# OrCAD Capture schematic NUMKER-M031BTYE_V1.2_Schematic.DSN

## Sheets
1 Nu-Link2-Me: size A3; title: Nu-Link2-Me; rev: 1.0; company: CMHuang; note: Nu-Link2-Me
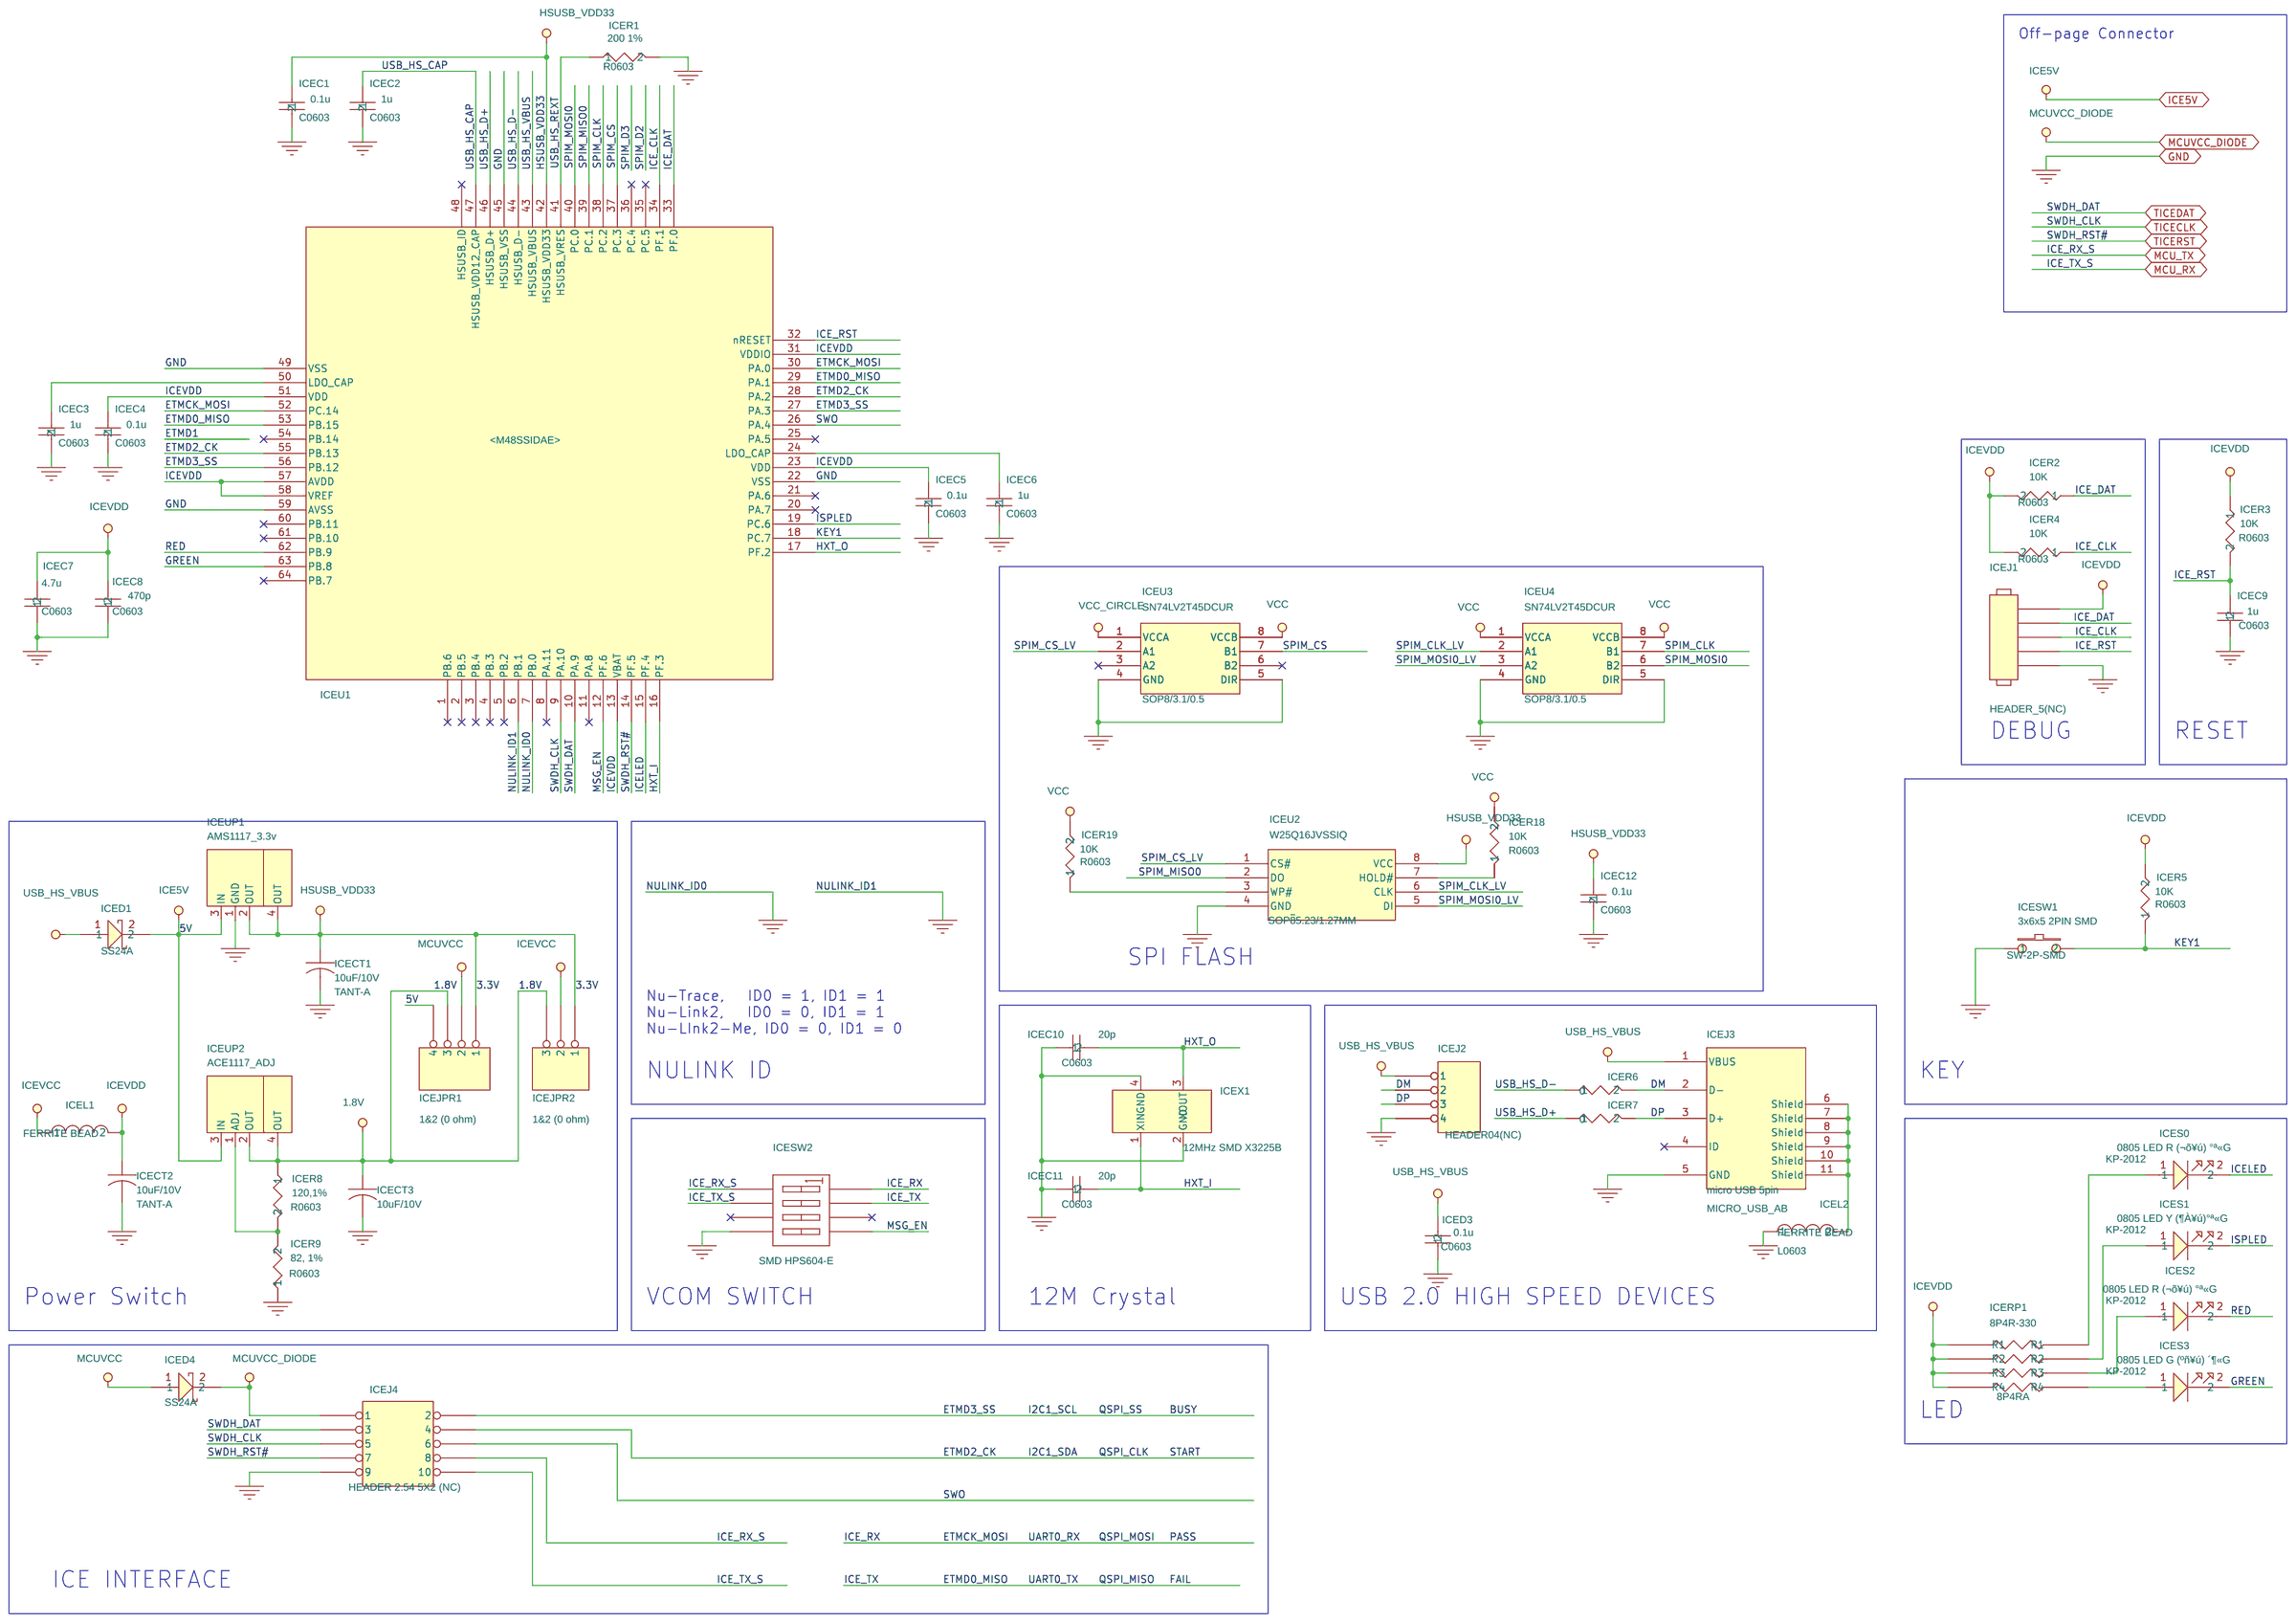
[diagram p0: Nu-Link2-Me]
2 M031BTYE3AN: size Custom; title: M031BTYE3AN; rev: v1.2; note: NuMaker-M031BTYE
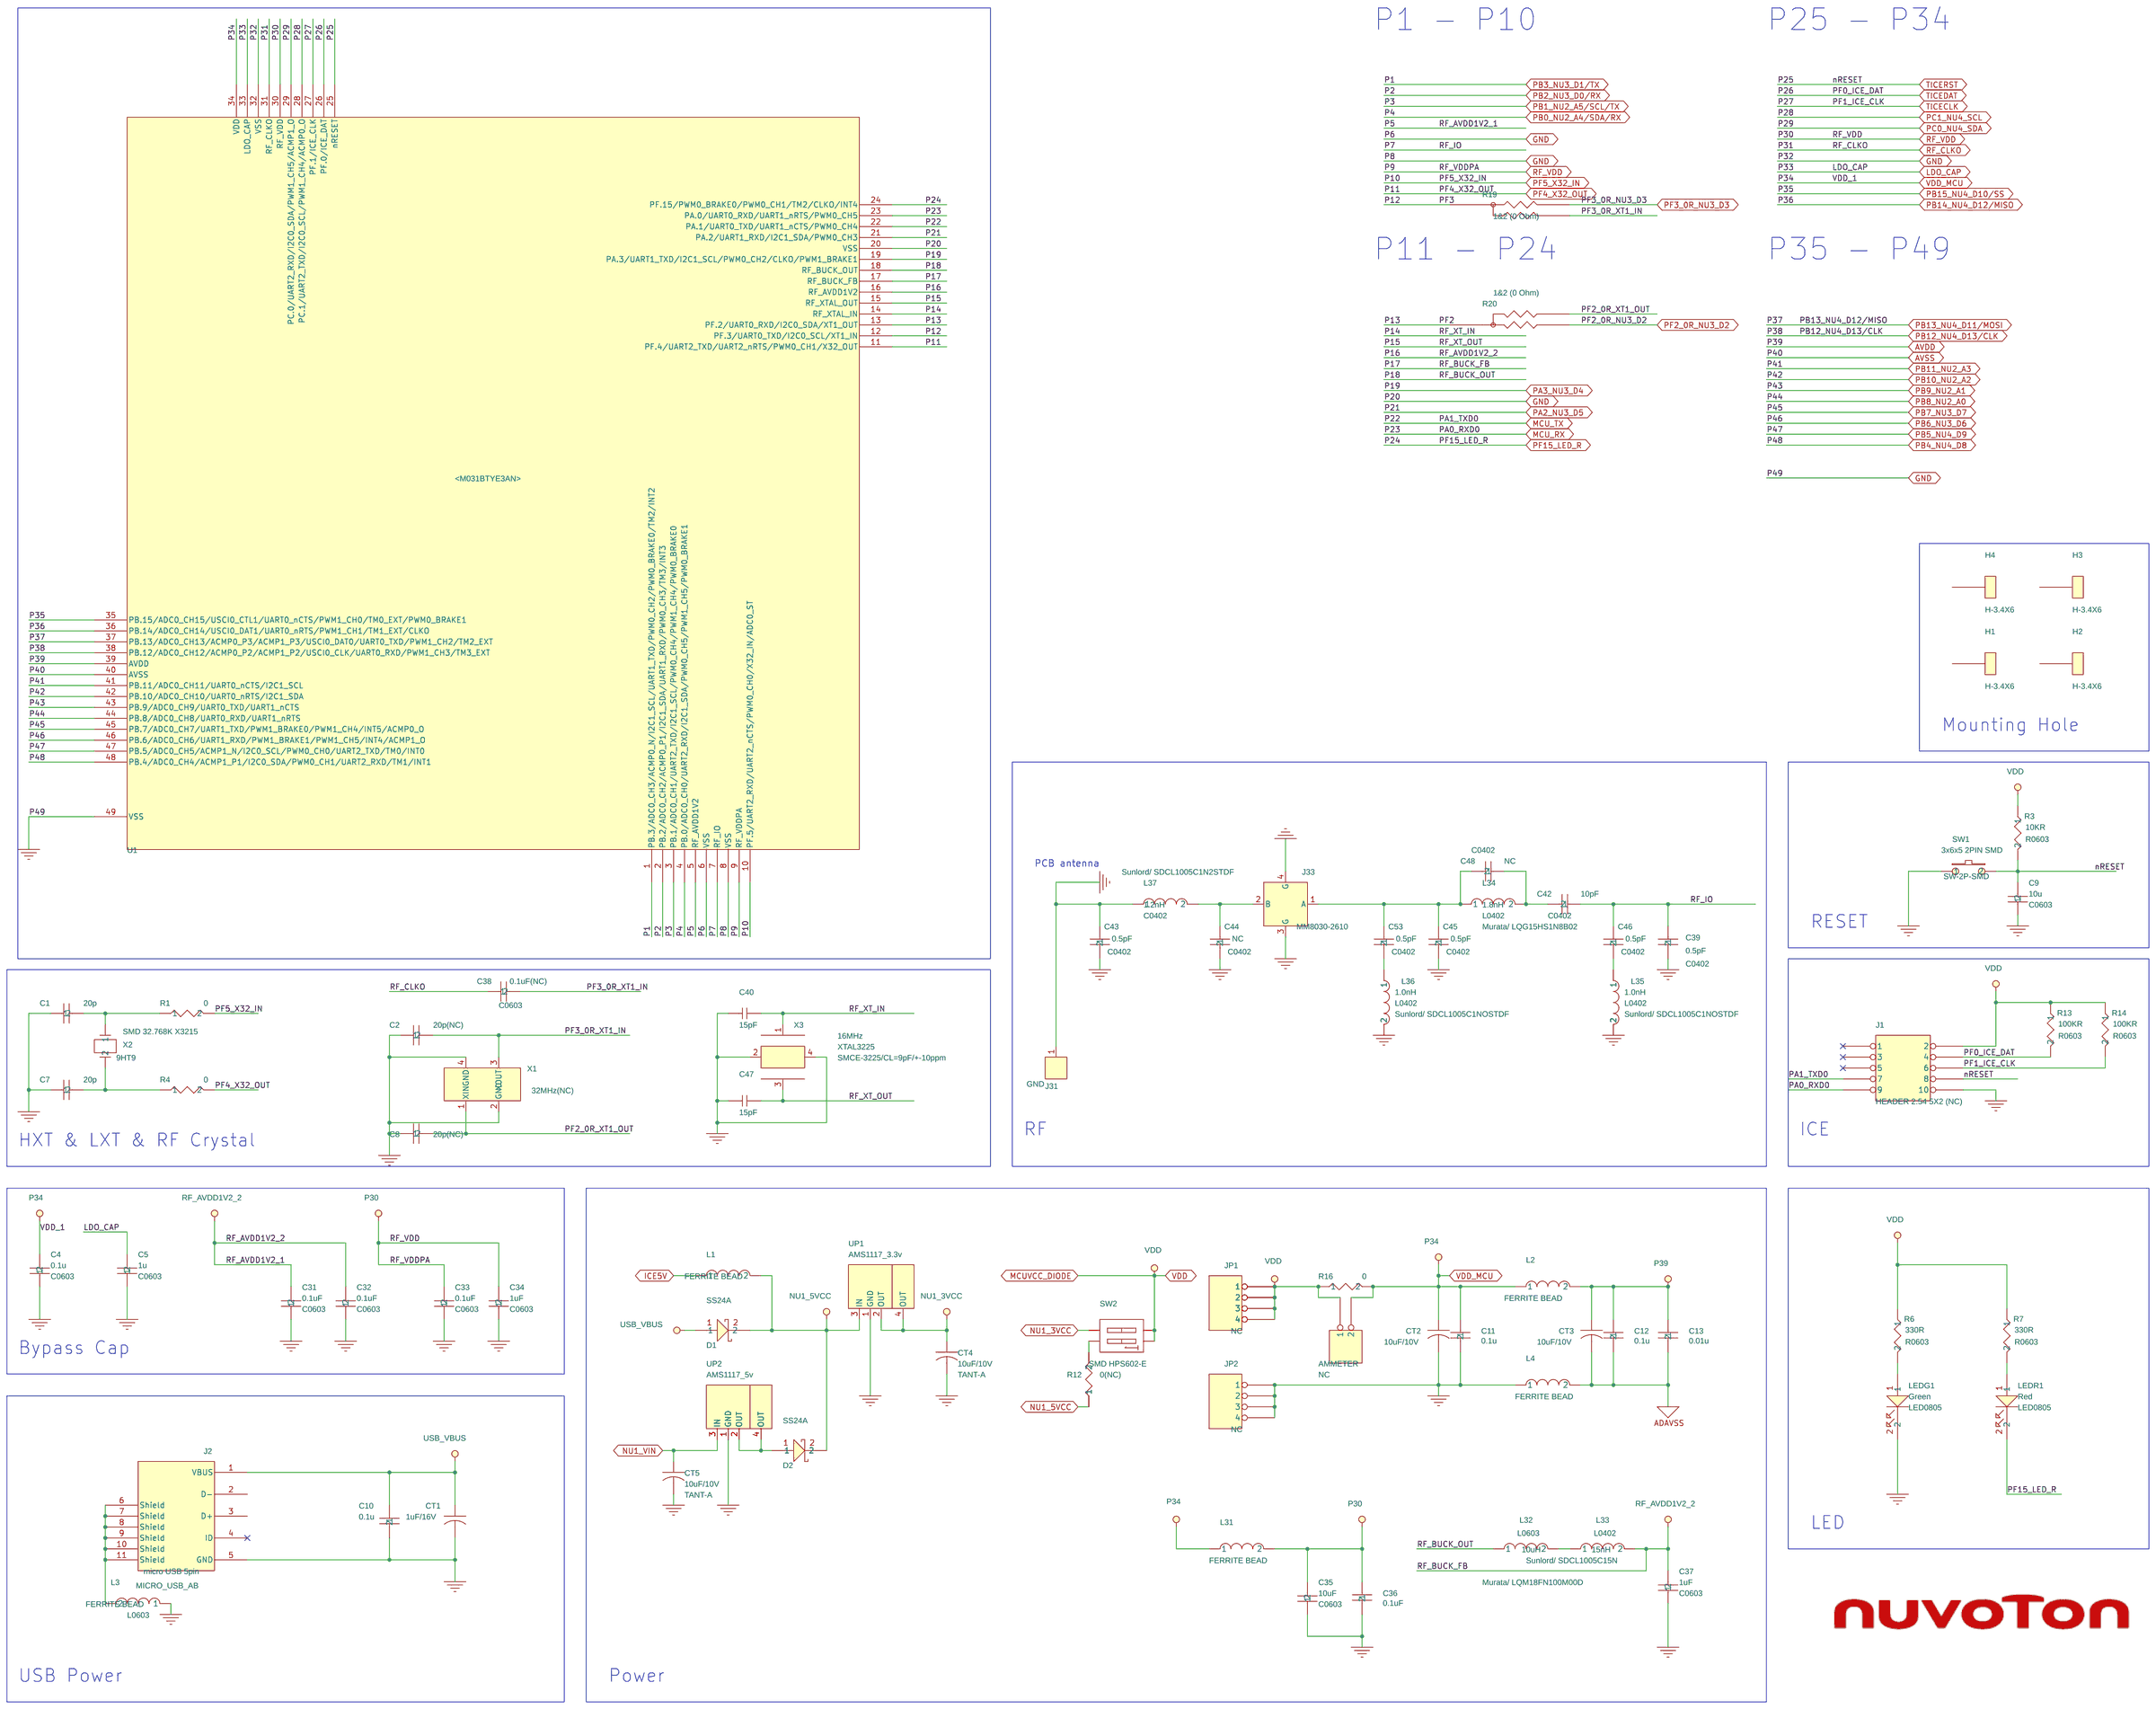
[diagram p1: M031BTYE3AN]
3 Ext. Connector: size Custom; title: Ext. Connector; rev: v1.2; note: NuMaker-M031BTYE
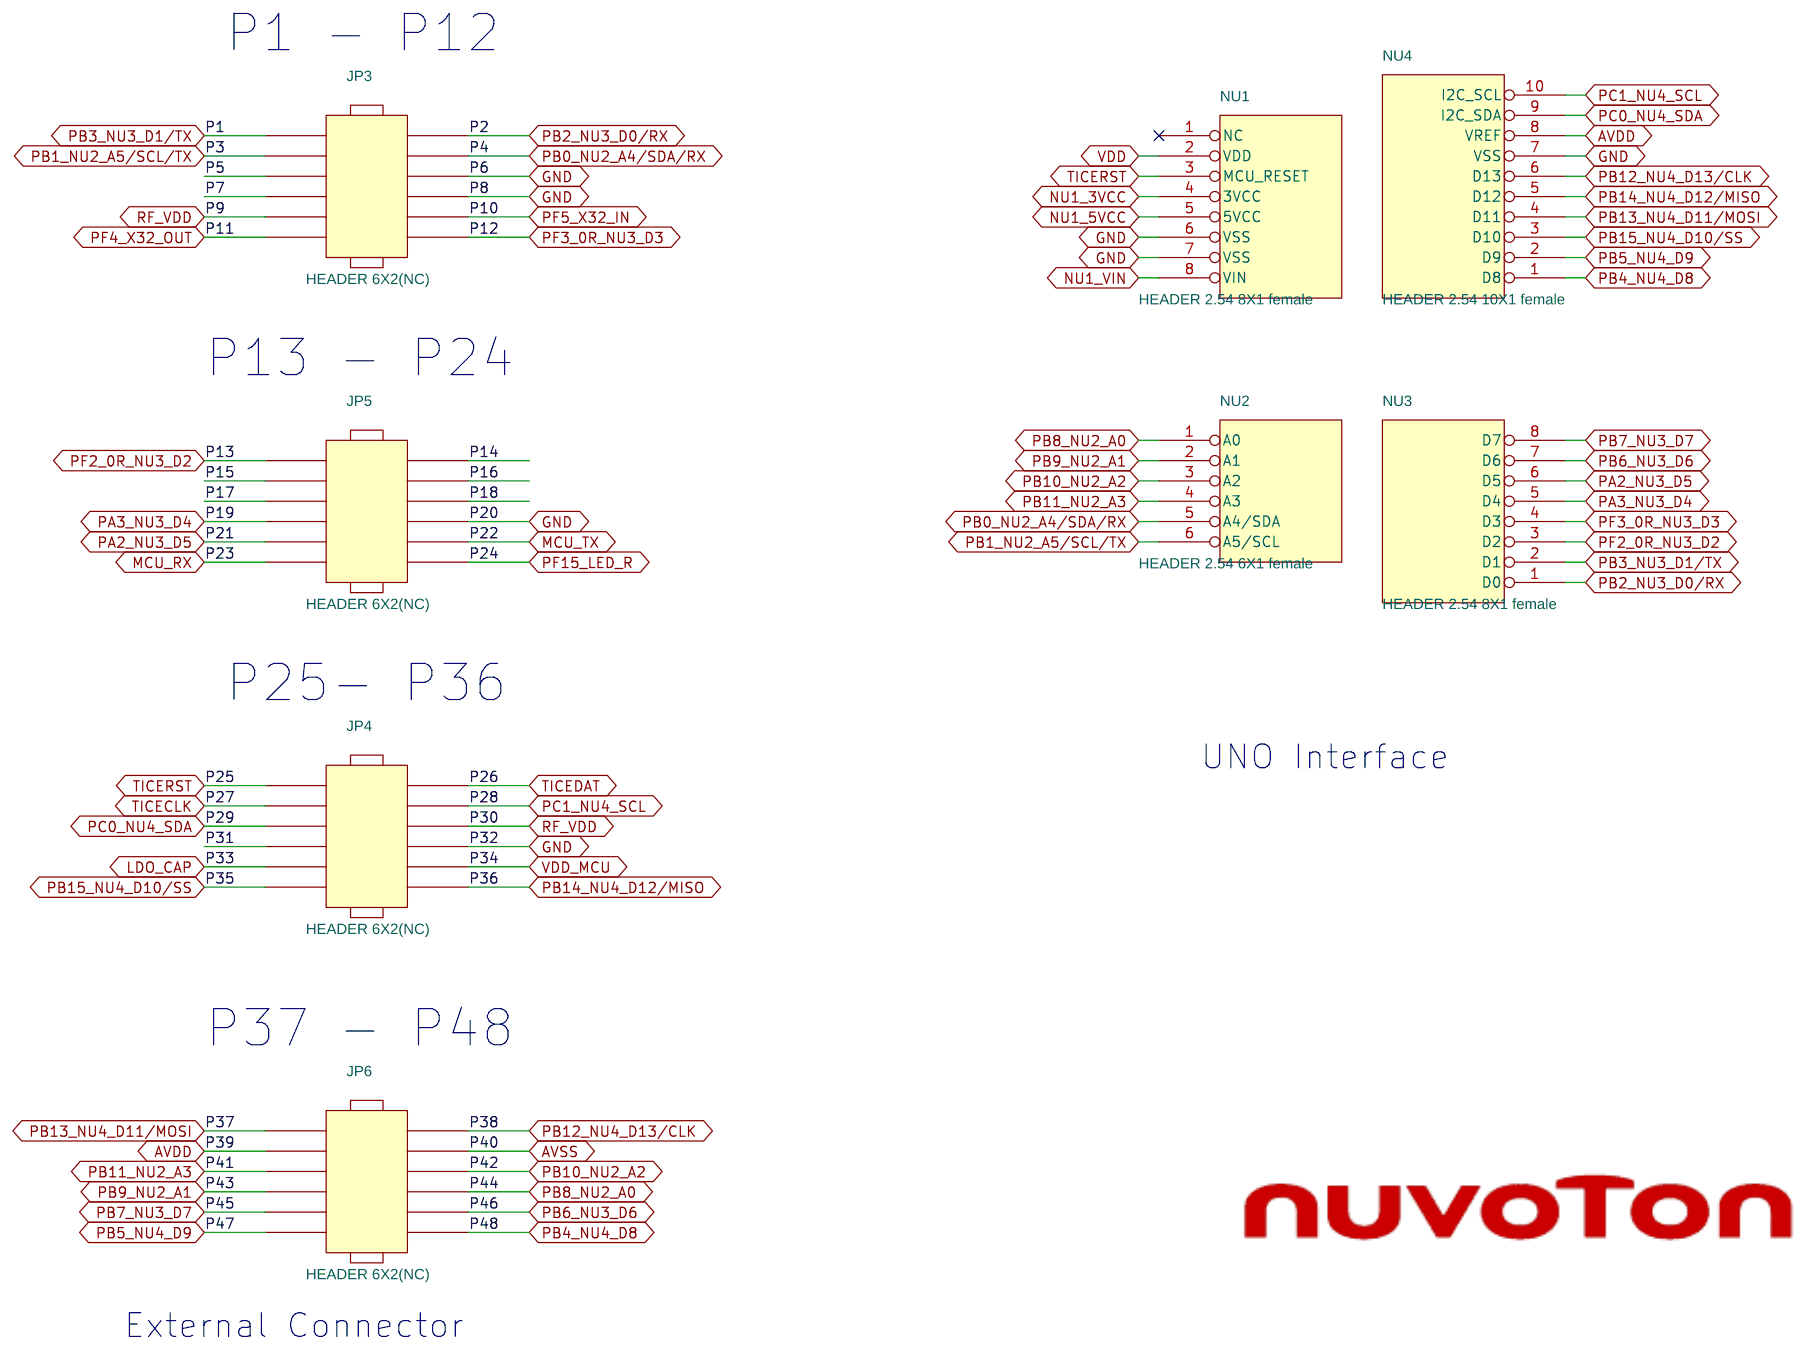
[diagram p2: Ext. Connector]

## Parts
sheet Ext. Connector
JP3  HEADER 6X2(NC)  [HEADER6X2]
JP4  HEADER 6X2(NC)  [HEADER6X2]
JP5  HEADER 6X2(NC)  [HEADER6X2]
JP6  HEADER 6X2(NC)  [HEADER6X2]
NU1  HEADER 2.54 8X1 female  [SIP-8P]
NU2  HEADER 2.54 6X1 female  [SIP-6P]
NU3  HEADER 2.54 8X1 female  [SIP-8P]
NU4  HEADER 2.54 10X1 female  [SIP-10P]
sheet M031BTYE3AN
AMMETER  NC
C1  20p  [C0603]
C2  20p(NC)  [C0603]
C4  0.1u  [C0603]
C5  1u  [C0603]
C7  20p  [C0603]
C8  20p(NC)  [C0603]
C9  10u  [C0603]
C10  0.1u  [C0603]
C11  0.1u  [C0603]
C12  0.1u  [C0603]
C13  0.01u  [C0603]
C31  0.1uF  [C0603]
C32  0.1uF  [C0603]
C33  0.1uF  [C0603]
C34  1uF  [C0603]
C35  10uF  [C0603]
C36  0.1uF  [C0603]
C37  1uF  [C0603]
C38  0.1uF(NC)  [C0603]
C39  0.5pF  [C0402]
C40  15pF  [C0402]
C42  10pF  [C0402]
C43  0.5pF  [C0402]
C44  NC  [C0402]
C45  0.5pF  [C0402]
C46  0.5pF  [C0402]
C47  15pF  [C0402]
C48  NC  [C0402]
C53  0.5pF  [C0402]
CT1  1uF/16V  [TANT-A]
CT2  10uF/10V  [TANT-A]
CT3  10uF/10V  [TANT-A]
CT4  10uF/10V  [TANT-A]
CT5  10uF/10V  [TANT-A]
D1  SS24A  [RB060L]
D2  SS24A  [RB060L]
H1  H-3.4X6  [H-3.4X6]
H2  H-3.4X6  [H-3.4X6]
H3  H-3.4X6  [H-3.4X6]
H4  H-3.4X6  [H-3.4X6]
J1  HEADER 2.54 5X2 (NC)  [HEADER5X2]
J2  micro USB 5pin  [MICRO_USB_AB]
J31  GND  [antenna_p]
J33  MM8030-2610  [MM8030-2610]
JP1  NC  [header1x4]
JP2  NC  [header1x4]
L1  FERRITE BEAD  [L0603]
L2  FERRITE BEAD  [L0603]
L3  FERRITE BEAD  [L0603]
L4  FERRITE BEAD  [L0603]
L31  FERRITE BEAD  [L0603]
L32  10uH  [L0603]
L33  15nH  [L0402]
L34  1.8nH  [L0402]
L35  1.0nH  [L0402]
L36  1.0nH  [L0402]
L37  1.2nH  [C0402]
LEDG1  Green  [LED0805]
LEDR1  Red  [LED0805]
R1  0  [R0603]
R3  10KR  [R0603]
R4  0  [R0603]
R6  330R  [R0603]
R7  330R  [R0603]
R12  0(NC)  [R0603]
R13  100KR  [R0603]
R14  100KR  [R0603]
R16  0  [R0603]
R19  1&2 (0 Ohm)  [R0603X2]
R20  1&2 (0 Ohm)  [R0603X2]
SW1  3x6x5 2PIN SMD  [SW-2P-SMD]
SW2  SMD HPS602-E  [SW1X2]
U1  M031BTYE3AN  [MCU_QFN48_5X5mm]
UP1  AMS1117_3.3v  [SOT-223-1]
UP2  AMS1117_5v  [SOT-223-1]
X1  32MHz(NC)  [XTAL3225]
X2  SMD 32.768K X3215  [9HT9]
X3  16MHz  [XTAL3225]
sheet Nu-Link2-Me
ICEC1  0.1u  [C0603]
ICEC2  1u  [C0603]
ICEC3  1u  [C0603]
ICEC4  0.1u  [C0603]
ICEC5  0.1u  [C0603]
ICEC6  1u  [C0603]
ICEC7  4.7u  [C0603]
ICEC8  470p  [C0603]
ICEC9  1u  [C0603]
ICEC10  20p  [C0603]
ICEC11  20p  [C0603]
ICEC12  0.1u  [C0603]
ICECT1  10uF/10V  [TANT-A]
ICECT2  10uF/10V  [TANT-A]
ICECT3  10uF/10V  [TANT-A]
ICED1  SS24A  [RB060L]
ICED3  0.1u  [C0603]
ICED4  SS24A  [RB060L]
ICEJ1  HEADER_5(NC)  [HEADER5X1]
ICEJ2  HEADER04(NC)  [HEADER04]
ICEJ3  micro USB 5pin  [MICRO_USB_AB]
ICEJ4  HEADER 2.54 5X2 (NC)  [HEADER5X2]
ICEJPR1  1&2 (0 ohm)  [R0603X3]
ICEJPR2  1&2 (0 ohm)  [R0603X2]
ICEL1  FERRITE BEAD  [L0603]
ICEL2  FERRITE BEAD  [L0603]
ICER1  200 1%  [R0603]
ICER2  10K  [R0603]
ICER3  10K  [R0603]
ICER4  10K  [R0603]
ICER5  10K  [R0603]
ICER6  0  [R0603]
ICER7  0  [R0603]
ICER8  120,1%  [R0603]
ICER9  82, 1%  [R0603]
ICER18  10K  [R0603]
ICER19  10K  [R0603]
ICERP1  8P4R-330  [8P4RA]
ICES0  0805 LED R (¬õ¥ú) °ª«G  [KP-2012]
ICES1  0805 LED Y (¶À¥ú)°ª«G  [KP-2012]
ICES2  0805 LED R (¬õ¥ú) °ª«G  [KP-2012]
ICES3  0805 LED G (ºñ¥ú) ´¶«G  [KP-2012]
ICESW1  3x6x5 2PIN SMD  [SW-2P-SMD]
ICESW2  SMD HPS604-E  [SW1X4]
ICEU1  M48SSIDAE  [LQFP64_7x7_M48SSIDAE]
ICEU2  W25Q16JVSSIQ  [SOP8\5.23/1.27MM]
ICEU3  SN74LV2T45DCUR  [SOP8/3.1/0.5]
ICEU4  SN74LV2T45DCUR  [SOP8/3.1/0.5]
ICEUP1  AMS1117_3.3v  [SOT-223-1]
ICEUP2  ACE1117_ADJ  [SOT-223-1]
ICEX1  12MHz SMD X3225B  [CRYSTAL_SMD]

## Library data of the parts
JP3-JP6 = HEADER_6X2
NU1 = POWER_CONNECT_0
NU2 = ADC_CONNECT_0
NU3 = PWM0_CONNECT_0
NU4 = PWM1_CONNECT_1
AMMETER = HEADER_2
C1 = C_20p_2
C2 = C_20p_3
C4 = CAP-C_8: Package: 0603; element_no: C0004
C5 = CAP-C_9: Package: 0603; element_no: C0006
C7 = C_20p_4
C8 = C_20p_1
C9 = CAP-C_2: Package: 0603; element_no: C0006
C10 = C_0.1u: element_no: C0004
C11 = C_0.1u_3: element_no: C0004
C12 = C_0.1u_2: element_no: C0004
C13 = C_0.1u_1: element_no: C0003
C31 ICED3 = CAP-C: Package: 0603; element_no: C0004
C32 ICEC5 = CAP-C_12: Package: 0603; element_no: C0004
C33 = CAP-C_14: Package: 0603; element_no: C0004
C34 = CAP-C_7: Package: 0603; element_no: C0004
C35 ICEC3 = CAP-C_10: Package: 0603; element_no: C0006
C36 = C_0.1u_4: element_no: C0004
C37 = CAP-C_16: Package: 0603; element_no: C0006
C38 = C_20p
C39 = CAP-C_13: Package: 0603
C40 C47 = CAPACITOR
C42 ICEC8 = CAP-C_1: Package: 0603
C43 = CAP-C_3: Package: 0603
C44 = CAP-C_4: Package: 0603
C45 = CAP-C_11: Package: 0603
C46 = CAP-C_5: Package: 0603
C48 = CAP-C_6: Package: 0603
C53 = CAP-C_15: Package: 0603
CT1 = C_1uF_16V
CT2-CT5 ICECT1-ICECT3 = C_10uF_10V
D1 ICED4 = D_SS24A_1
D2 ICED1 = D_SS24A
H1-H4 = TEST_POINT
ICEJ4 J1 = HEADER_5X2
ICEJ3 J2 = micro_USB_5pin_0
J31 = JUMPER3X1_0
J33 = JUMPER3X1_4
ICEJ2 JP1 = HEADER_4
JP2 = HEADER_4_1
ICEL2 L1 = FERRITE_BEAD_1
L2 = FERRITE_BEAD_3
L3 = FERRITE_BEAD_4
ICEL1 L4 = FERRITE_BEAD
L31 = FERRITE_BEAD_2
L32 = INDUCTOR_1: Part Number: Murata/ LQM18FN100M00D
L33 = INDUCTOR: Package: L0603; Part Number: Sunlord/ SDCL1005C15N
L34 = INDUCTOR_3: Package: L0603; Part Number: Murata/ LQG15HS1N8B02
L35 = INDUCTOR_2: Package: L0603; Part Number: Sunlord/ SDCL1005C1NOSTDF
L36 = INDUCTOR_5: Package: L0603; Part Number: Sunlord/ SDCL1005C1NOSTDF
L37 = INDUCTOR_4: Package: L0603; Part Number: Sunlord/ SDCL1005C1N2STDF
LEDG1 = LED_0_1: Package: KP-2012; Vendor: Kingbright
LEDR1 = LED_0: Package: KP-2012; Vendor: Kingbright
R1 = R_0_7
ICER9 R3 = R_0: Package: 0603
R4 = R_0_4
ICER1 R6 = R_0_6: Package: 0603
ICER5 R7 = R_0_2: Package: 0603
R12 = R_0_1
ICER8 R13 = R_0_3: Package: 0603
ICER2 R14 = R_0_5: Package: 0603
R16 = R_0_8
R19 R20 = RESISTOR_SIP_3_0
ICESW1 SW1 = SW_PUSHBUTTON_0
SW2 = SW_DIP-4_2
U1 = M031BTYE3AN_4: M031LE3AE: <M031BTYE3AN>
ICEUP1 UP1 UP2 = TO-247_Regulator_10
X1 = Crystal_SMD_3
X2 = Xtal_32.768K
X3 = X_0: Part Number: SMCE-3225/CL=9pF/+-10ppm
ICEC1 = CAP-C_4: Package: 0603; element_no: C0004
ICEC2 = CAP-C_6: Package: 0603; element_no: C0006
ICEC4 = CAP-C_11: Package: 0603; element_no: C0004
ICEC6 = CAP-C_5: Package: 0603; element_no: C0006
ICEC7 = CAP-C_9: Package: 0603
ICEC9 = CAP-C_8: Package: 0603; element_no: C0006
ICEC10 = CAP-C_7: Package: 0603
ICEC11 = CAP-C_2: Package: 0603
ICEC12 = CAP-C_3: Package: 0603; element_no: C0004
ICEJ1 = HEADER_5
ICEJPR1 = HEADER_3_0
ICEJPR2 = HEADER_3
ICER3 = R_0_7: Package: 0603
ICER4 = R_0_8: Package: 0603
ICER6 = R_33
ICER7 = R_33_1
ICER18 = R_0_4: Package: 0603
ICER19 = R_0_1: Package: 0603
ICERP1 = R-PACK8_0
ICES0 = LED_0_1: Vendor: Kingbright
ICES1 = LED_0: Vendor: Kingbright
ICES2 = LED_0_2: Vendor: Kingbright
ICES3 = LED_0_3: Vendor: Kingbright
ICESW2 = SW_DIP-4_SM
ICEU1 = M487SIDAE_0: M487SIDAE: <M48SSIDAE>
ICEU2 = W25P10_20_40_SOIC_0: Package: SOP8; Vendor: WINBOND
ICEU3 ICEU4 = SN74LV2T45
ICEUP2 = TO-247_Regulator_0
ICEX1 = Crystal_SMD_4

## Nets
1.8V: ICECT3.1 ICEJPR1.3 ICEJPR2.3 ICER8.1 ICEUP2.2(OUT) ICEUP2.4(OUT)
3.3V: ICEC1.1 ICEC12.1 ICECT1.1 ICEJPR1.1 ICEJPR2.1 ICER18.2 ICER19.2 ICEU1.42(HSUSB_VDD33) ICEU2.8(VCC) ICEU3.1(VCCA) ICEU4.1(VCCA) ICEUP1.2(OUT) ICEUP1.4(OUT)
AVDD: C12.1 C13.1 CT3.1 JP6.3 L2.2 NU4.8(VREF) U1.39(AVDD)
AVSS: C12.2 C13.2 CT3.2 JP6.4 L4.2 U1.40(AVSS)
GND: C1.1 C2.1 C4.1 C5.1 C7.1 C8.1 C9.1 C10.2 C11.2 C31.1 C32.1 C33.1 C34.1 C35.1 C36.2 C37.1 C39.2 C40.1 C43.1 C43.2 C44.2 C45.2 C47.1 CT1.2 CT2.2 CT4.2 CT5.2 ICEC1.2 ICEC2.2 ICEC3.2 ICEC4.2 ICEC5.2 ICEC6.2 ICEC7.1 ICEC8.1 ICEC9.1 ICEC10.1 ICEC11.1 ICEC12.2 ICECT1.2 ICECT2.2 ICECT3.2 ICED3.1 ICEJ1.5 ICEJ2.4 ICEJ3.5(GND) ICEJ4.9 ICEL2.1 ICER1.2 ICER9.1 ICESW1.1 ICESW2.4(A4) ICEU1.6(PB.1) ICEU1.7(PB.0) ICEU1.22(VSS) ICEU1.45(HSUSB_VSS) ICEU1.49(VSS) ICEU1.59(AVSS) ICEU2.4(GND) ICEU3.4(GND) ICEU3.5(DIR) ICEU4.4(GND) ICEU4.5(DIR) ICEUP1.1(GND) ICEX1.2(GND) ICEX1.4(GND) J1.10 J2.5(GND) J31.1 J33.3(G) J33.4(G) JP2.1 JP2.2 JP2.3 JP2.4 JP3.6 JP3.8 JP4.8 JP5.8 L3.1 L4.1 L35.2 L36.2 L37.1 LEDG1.2 NU1.6(VSS) NU1.7(VSS) NU4.7(VSS) SW1.1 U1.6(VSS) U1.8(VSS) U1.20(VSS) U1.32(VSS) U1.49(VSS) UP1.1(GND) UP2.1(GND) X1.2(GND) X1.4(GND) X3.2 X3.4
VDD: AMMETER.1 ICED4.2 ICEJ4.1 J1.2 JP1.1 JP1.2 JP1.3 JP1.4 NU1.2(VDD) R3.1 R6.1 R7.1 R13.1 R14.1 R16.1 SW2.3(B1) SW2.4(B2)
VDD_MCU: AMMETER.2 C4.2 C11.1 CT2.1 JP4.10 L2.1 L31.1 R16.2 U1.34(VDD)
BUSY: ICEJ4.2 ICEU1.27(PA.3) ICEU1.56(PB.12)
DM: ICEJ2.2 ICEJ3.2(D-) ICER6.2
DP: ICEJ2.3 ICEJ3.3(D+) ICER7.2
ETMD2_CK: ICEJ4.4 ICEU1.28(PA.2) ICEU1.55(PB.13)
GREEN: ICES3.2 ICEU1.63(PB.8)
HXT_I: ICEC11.2 ICEU1.16(PF.3) ICEX1.1(XIN)
HXT_O: ICEC10.2 ICEU1.17(PF.2) ICEX1.3(XOUT)
ICE5V: ICED1.2 ICEJPR1.4 ICEUP1.3(IN) ICEUP2.3(IN) L1.1
ICE_CLK: ICEJ1.3 ICER4.1 ICEU1.34(PF.1)
ICE_DAT: ICEJ1.2 ICER2.1 ICEU1.33(PF.0)
ICE_RST: ICEC9.2 ICEJ1.4 ICER3.2 ICEU1.32(nRESET)
ICE_RX: ICESW2.8(B1) ICEU1.30(PA.0) ICEU1.52(PC.14)
ICE_TX: ICESW2.7(B2) ICEU1.29(PA.1) ICEU1.53(PB.15)
ICELED: ICES0.2 ICEU1.15(PF.4)
ICEVCC: ICEJPR2.2 ICEL1.1
ICEVDD: ICEC4.1 ICEC5.1 ICEC7.2 ICEC8.2 ICECT2.1 ICEJ1.1 ICEL1.2 ICER2.2 ICER3.1 ICER4.2 ICER5.2 ICERP1.1(R1) ICERP1.3(R2) ICERP1.5(R3) ICERP1.7(R4) ICEU1.13(VBAT) ICEU1.23(VDD) ICEU1.31(VDDIO) ICEU1.51(VDD) ICEU1.57(AVDD) ICEU1.58(VREF) ICEU3.8(VCCB) ICEU4.8(VCCB)
ISPLED: ICES1.2 ICEU1.19(PC.6)
KEY1: ICER5.1 ICESW1.2 ICEU1.18(PC.7)
LDO_CAP: C5.2 JP4.9 U1.33(LDO_CAP)
MCU_RX: ICEJ4.10 ICESW2.2(A2) J1.9 JP5.11 U1.23(PA.0/UART0_RXD/UART1_nRTS/PWM0_CH5)
MCU_TX: ICEJ4.8 ICESW2.1(A1) J1.7 JP5.10 U1.22(PA.1/UART0_TXD/UART1_nCTS/PWM0_CH4)
MCUVCC: ICED4.1 ICEJPR1.2
MSG_EN: ICESW2.5(B4) ICEU1.12(PF.6)
NU1_3VCC: CT4.1 NU1.4(3VCC) SW2.2(A2) UP1.2(OUT) UP1.4(OUT)
NU1_5VCC: D1.2 D2.2 L1.2 NU1.5(5VCC) R12.1 UP1.3(IN)
NU1_VIN: CT5.1 NU1.8(VIN) UP2.3(IN)
P5: JP3.5
P7: C39.1 C42.1 C46.1 U1.7(RF_IO)
P7 (page 03-Ext. Connector): JP3.7
P14: C40.2 U1.14(RF_XTAL_IN) X3.1
P14 (page 03-Ext. Connector): JP5.2
P15: C47.2 U1.15(RF_XTAL_OUT) X3.3
P15 (page 03-Ext. Connector): JP5.3
P16: JP5.4
P17: JP5.5
P18: L32.1 U1.18(RF_BUCK_OUT)
P18 (page 03-Ext. Connector): JP5.6
P31: JP4.7
PA2_NU3_D5: JP5.9 NU3.6(D5) U1.21(PA.2/UART1_RXD/I2C1_SDA/PWM0_CH3)
PA3_NU3_D4: JP5.7 NU3.5(D4) U1.19(PA.3/UART1_TXD/I2C1_SCL/PWM0_CH2/CLKO/PWM1_BRAKE1)
PB0_NU2_A4/SDA/RX: JP3.4 NU2.5(A4/SDA) U1.4(PB.0/ADC0_CH0/UART2_RXD/I2C1_SDA/PWM0_CH5/PWM1_CH5/PWM0_BRAKE1)
PB1_NU2_A5/SCL/TX: JP3.3 NU2.6(A5/SCL) U1.3(PB.1/ADC0_CH1/UART2_TXD/I2C1_SCL/PWM0_CH4/PWM1_CH4/PWM0_BRAKE0)
PB2_NU3_D0/RX: JP3.2 NU3.1(D0) U1.2(PB.2/ADC0_CH2/ACMP0_P1/I2C1_SDA/UART1_RXD/PWM0_CH3/TM3/INT3)
PB3_NU3_D1/TX: JP3.1 NU3.2(D1) U1.1(PB.3/ADC0_CH3/ACMP0_N/I2C1_SCL/UART1_TXD/PWM0_CH2/PWM0_BRAKE0/TM2/INT2)
PB4_NU4_D8: JP6.12 NU4.1(D8) U1.48(PB.4/ADC0_CH4/ACMP1_P1/I2C0_SDA/PWM0_CH1/UART2_RXD/TM1/INT1)
PB5_NU4_D9: JP6.11 NU4.2(D9) U1.47(PB.5/ADC0_CH5/ACMP1_N/I2C0_SCL/PWM0_CH0/UART2_TXD/TM0/INT0)
PB6_NU3_D6: JP6.10 NU3.7(D6) U1.46(PB.6/ADC0_CH6/UART1_RXD/PWM1_BRAKE1/PWM1_CH5/INT4/ACMP1_O)
PB7_NU3_D7: JP6.9 NU3.8(D7) U1.45(PB.7/ADC0_CH7/UART1_TXD/PWM1_BRAKE0/PWM1_CH4/INT5/ACMP0_O)
PB8_NU2_A0: JP6.8 NU2.1(A0) U1.44(PB.8/ADC0_CH8/UART0_RXD/UART1_nRTS)
PB9_NU2_A1: JP6.7 NU2.2(A1) U1.43(PB.9/ADC0_CH9/UART0_TXD/UART1_nCTS)
PB10_NU2_A2: JP6.6 NU2.3(A2) U1.42(PB.10/ADC0_CH10/UART0_nRTS/I2C1_SDA)
PB11_NU2_A3: JP6.5 NU2.4(A3) U1.41(PB.11/ADC0_CH11/UART0_nCTS/I2C1_SCL)
PB12_NU4_D13/CLK: JP6.2 NU4.6(D13) U1.38(PB.12/ADC0_CH12/ACMP0_P2/ACMP1_P2/USCI0_CLK/UART0_RXD/PWM1_CH3/TM3_EXT)
PB13_NU4_D11/MOSI: JP6.1 NU4.4(D11) U1.37(PB.13/ADC0_CH13/ACMP0_P3/ACMP1_P3/USCI0_DAT0/UART0_TXD/PWM1_CH2/TM2_EXT)
PB14_NU4_D12/MISO: JP4.12 NU4.5(D12) U1.36(PB.14/ADC0_CH14/USCI0_DAT1/UART0_nRTS/PWM1_CH1/TM1_EXT/CLKO)
PB15_NU4_D10/SS: JP4.11 NU4.3(D10) U1.35(PB.15/ADC0_CH15/USCI0_CTL1/UART0_nCTS/PWM1_CH0/TM0_EXT/PWM0_BRAKE1)
PC0_NU4_SDA: JP4.5 NU4.9(I2C_SDA) U1.29(PC.0/UART2_RXD/I2C0_SDA/PWM1_CH5/ACMP1_O)
PC1_NU4_SCL: JP4.4 NU4.10(I2C_SCL) U1.28(PC.1/UART2_TXD/I2C0_SCL/PWM1_CH4/ACMP0_O)
PF2: R20.2 U1.13(PF.2/UART0_RXD/I2C0_SDA/XT1_OUT)
PF2_0R_NU3_D2: JP5.1 NU3.3(D2) R20.1
PF2_0R_XT1_OUT: C8.2 R20.3 X1.1(XIN)
PF3: R19.2 U1.12(PF.3/UART0_TXD/I2C0_SCL/XT1_IN)
PF3_0R_NU3_D3: JP3.12 NU3.4(D3) R19.1
PF3_0R_XT1_IN: C2.2 C38.2 R19.3 X1.3(XOUT)
PF4_X32_OUT: JP3.11 R4.2 U1.11(PF.4/UART2_TXD/UART2_nRTS/PWM0_CH1/X32_OUT)
PF5_X32_IN: JP3.10 R1.2 U1.10(PF.5/UART2_RXD/UART2_nCTS/PWM0_CH0/X32_IN/ADC0_ST)
PF15_LED_R: JP5.12 LEDR1.2 U1.24(PF.15/PWM0_BRAKE0/PWM0_CH1/TM2/CLKO/INT4)
RED: ICES2.2 ICEU1.62(PB.9)
RF_AVDD1V2: C31.2 C32.2 C37.2 L33.2 U1.5(RF_AVDD1V2) U1.16(RF_AVDD1V2) U1.17(RF_BUCK_FB)
RF_CLKO: C38.1 U1.31(RF_CLKO)
RF_VDD: C33.2 C34.2 C35.2 C36.1 JP3.9 JP4.6 L31.2 U1.9(RF_VDDPA) U1.30(RF_VDD)
SPIM_CLK: ICEU1.38(PC.2) ICEU4.7(B1)
SPIM_CLK_LV: ICEU2.6(CLK) ICEU4.2(A1)
SPIM_CS: ICEU1.37(PC.3) ICEU3.7(B1)
SPIM_CS_LV: ICEU2.1(CS#) ICEU3.2(A1)
SPIM_MISO0: ICEU1.39(PC.1) ICEU2.2(DO)
SPIM_MOSI0: ICEU1.40(PC.0) ICEU4.6(B2)
SPIM_MOSI0_LV: ICEU2.5(DI) ICEU4.3(A2)
SWO: ICEJ4.6 ICEU1.26(PA.4)
TICECLK: ICEJ4.5 ICEU1.9(PA.10) J1.6 JP4.3 R14.2 U1.27(PF.1/ICE_CLK)
TICEDAT: ICEJ4.3 ICEU1.10(PA.9) J1.4 JP4.2 R13.2 U1.26(PF.0/ICE_DAT)
TICERST: C9.2 ICEJ4.7 ICEU1.14(PF.5) J1.8 JP4.1 NU1.3(MCU_RESET) R3.2 SW1.2 U1.25(nRESET)
USB_HS_CAP: ICEC2.1 ICEU1.47(HSUSB_VDD12_CAP)
USB_HS_D+: ICER7.1 ICEU1.46(HSUSB_D+)
USB_HS_D-: ICER6.1 ICEU1.44(HSUSB_D-)
USB_HS_REXT: ICER1.1 ICEU1.41(HSUSB_VRES)
USB_HS_VBUS: ICED1.1 ICED3.2 ICEJ2.1 ICEJ3.1(VBUS) ICEU1.43(HSUSB_VBUS)
USB_VBUS: C10.1 CT1.1 D1.1 J2.1(VBUS)
N17408794: ICEC6.1 ICEU1.24(LDO_CAP)
N17408892: ICEC3.1 ICEU1.50(LDO_CAP)
N17409469: ICER18.1 ICEU2.7(HOLD#)
N17409471: ICER19.1 ICEU2.3(WP#)
N17409655: ICEJ3.6(Shield) ICEJ3.7(Shield) ICEJ3.8(Shield) ICEJ3.9(Shield) ICEJ3.10(Shield) ICEJ3.11(Shield) ICEL2.2
N17409830: ICERP1.8(R4) ICES3.1
N17409832: ICERP1.6(R3) ICES2.1
N17409866: ICERP1.4(R2) ICES1.1
N17409872: ICERP1.2(R1) ICES0.1
N17410019: ICER8.2 ICER9.2 ICEUP2.1(ADJ)
N17412799: C53.2 L36.1
N17412801: C45.1 C48.2 C53.1 J33.1(A) L34.1
N17412817: C46.2 L35.1
N17412836: C42.2 C48.1 L34.2
N17413278: C1.2 R1.1 X2.1
N17413280: C7.2 R4.1 X2.2
N17413523: C44.1 J33.2(B) L37.2
N17413703: J2.6(Shield) J2.7(Shield) J2.8(Shield) J2.9(Shield) J2.10(Shield) J2.11(Shield) L3.2
N17414005: LEDG1.1 R6.2
N17414007: LEDR1.1 R7.2
N17414019: R12.2 SW2.1(A1)
N17414057: D2.1 UP2.2(OUT) UP2.4(OUT)
N17414383: L32.2 L33.1

Not connected (* = marked no-connect by the designer): H1 1; H2 1; H3 1; H4 1; ICEJ3 4(ID)*; ICESW2 3(A3)* 6(B3)*; ICEU1 1(PB.6)* 2(PB.5)* 3(PB.4)* 4(PB.3)* 5(PB.2)* 8(PA.11)* 11(PA.8)* 20(PA.7)* 21(PA.6)* 25(PA.5)* 35(PC.5)* 36(PC.4)* 48(HSUSB_ID)* 54(PB.14)* 60(PB.11)* 61(PB.10)* 64(PB.7)*; ICEU3 3(A2)* 6(B2)*; J1 1* 3* 5*; J2 2(D-) 3(D+) 4(ID)*; NU1 1(NC)*

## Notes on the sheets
sheet 1
- Off-page Connector
- DEBUG
- RESET
- SPI FLASH
- Nu-Trace,   ID0 = 1, ID1 = 1
  Nu-Link2,   ID0 = 0, ID1 = 1
  Nu-LInk2-Me, ID0 = 0, ID1 = 0
- NULINK ID
- KEY
- Power Switch
- VCOM SWITCH
- 12M Crystal
- USB 2.0 HIGH SPEED DEVICES
- LED
- ICE INTERFACE
sheet 2
- P1 - P10
- P25 - P34
- P11 - P24
- P35 - P49
- Mounting Hole
- PCB antenna
- RESET
- RF
- ICE
- HXT & LXT & RF Crystal
- Bypass Cap
- LED
- USB Power
- Power
sheet 3
- P1 - P12
- P13 - P24
- P25- P36
- UNO Interface
- P37 - P48
- External Connector
